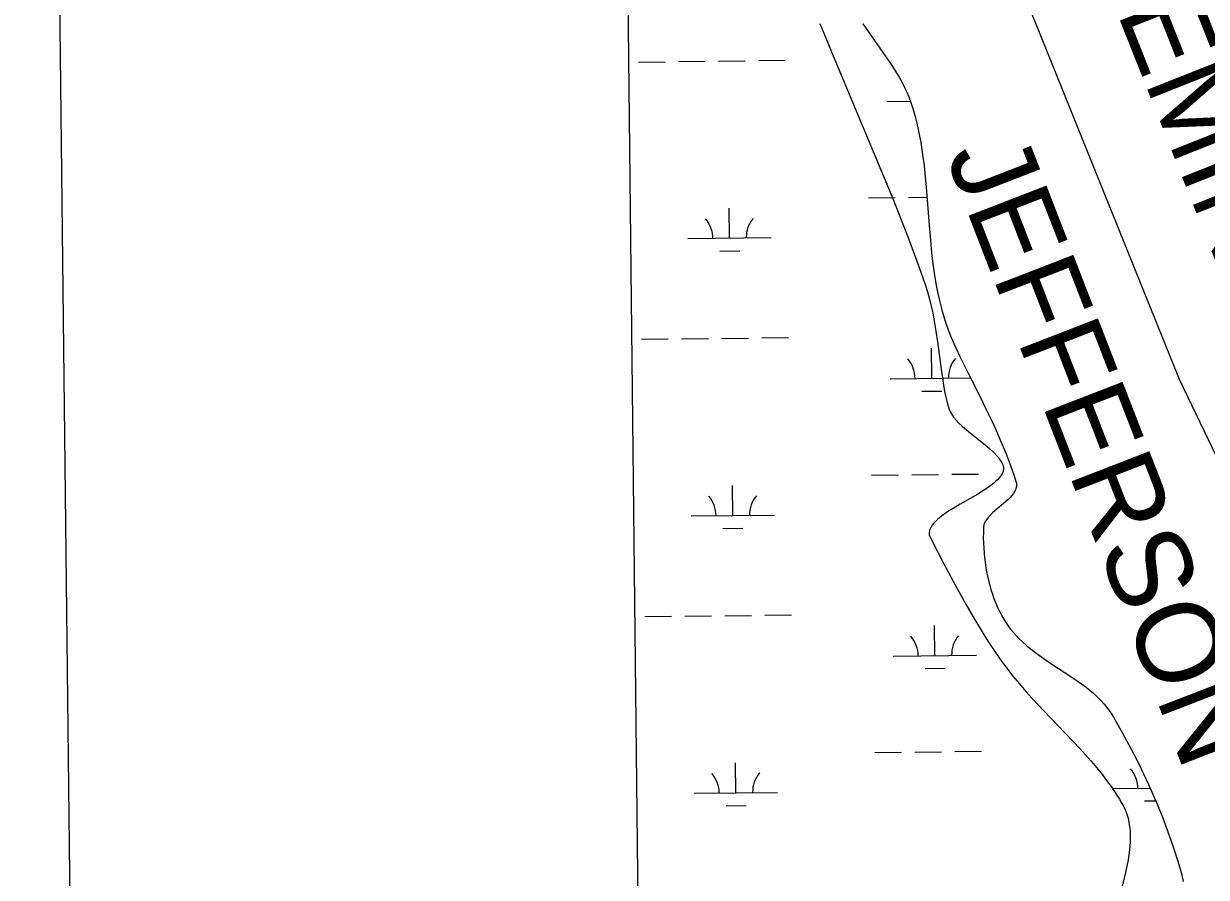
# Model space of a CAD drawing. Extents: x 3678539 to 3716648, y 451386 to 477139.
# Drawn here: x 3681880 to 3683298, y 470744 to 471768 of the extents above; entities that cross this region are included whole.
import ezdxf

# ---------------------------------------------------------------- set-up
doc = ezdxf.new("R2010")
doc.units = 0
for name, color, linetype in [('V-ANNO-SYMB', 7, 'Continuous'), ('V-GRID-FRAM', 7, 'Continuous'), ('V-SITE-VEGE', 7, 'Continuous'), ('V-TOPO-BNDY', 7, 'Continuous'), ('V-TOPO-GNAM-IDEN', 7, 'Continuous'), ('V-TOPO-SHOR', 7, 'Continuous'), ('V-WETL-SWMP', 7, 'Continuous')]:
    doc.layers.add(name, color=color, linetype=linetype)

msp = doc.modelspace()

# ---------------------------------------------------------------- linework, layer by layer
at = {"layer": 'V-ANNO-SYMB'}
msp.add_lwpolyline([(3682143.1, 452625.9), (3715224.1, 453006), (3714960.8, 475921.1), (3681879.8, 475540.9), (3682143.1, 452625.9)], dxfattribs=at)
at = {"layer": 'V-GRID-FRAM'}
msp.add_lwpolyline([(3682569.5, 474981.5), (3714284.1, 475345.9), (3714501, 457164.6), (3682770.5, 456800), (3682569.5, 474981.5)], dxfattribs=at)
at = {"layer": 'V-SITE-VEGE'}
for p, q in [((3682646.4, 468024.3), (3682598.3, 472383.5)), ((3682834.3, 471768.7), (3682850.4, 471729.6)), ((3682850.4, 471729.6), (3682907.7, 471593)), ((3682907.7, 471593), (3682921.7, 471558.7)), ((3682921.7, 471558.7), (3682931.9, 471533)), ((3682931.9, 471533), (3682939.4, 471513.7)), ((3682939.4, 471513.7), (3682950.3, 471484.7)), ((3682950.3, 471484.7), (3682955.5, 471470.1)), ((3682955.5, 471470.1), (3682960.7, 471455.5)), ((3682960.7, 471455.5), (3682963.6, 471446.5)), ((3682963.6, 471446.5), (3682966, 471437.7)), ((3682966, 471437.7), (3682968, 471429.3)), ((3682968, 471429.3), (3682969.7, 471421.3)), ((3682969.7, 471421.3), (3682971.1, 471413.7)), ((3682971.1, 471413.7), (3682973.4, 471399.3)), ((3682973.4, 471399.3), (3682975.3, 471386.7)), ((3682975.3, 471386.7), (3682980.1, 471350.9)), ((3682980.1, 471350.9), (3682982.6, 471334.6)), ((3682982.6, 471334.6), (3682984, 471327.1)), ((3682984, 471327.1), (3682985.1, 471321.8)), ((3682985.1, 471321.8), (3682987, 471314)), ((3682987, 471314), (3682989.1, 471306.7)), ((3682989.1, 471306.7), (3682989.9, 471304.5)), ((3682989.9, 471304.5), (3682990.9, 471302.3)), ((3682990.9, 471302.3), (3682992.1, 471300.2)), ((3682992.1, 471300.2), (3682993.4, 471298.2)), ((3682993.4, 471298.2), (3682994.8, 471296.3)), ((3682994.8, 471296.3), (3682997.9, 471292.5)), ((3682997.9, 471292.5), (3683001.2, 471289.1)), ((3683001.2, 471289.1), (3683004.5, 471285.9)), ((3683004.5, 471285.9), (3683007.9, 471282.9)), ((3683007.9, 471282.9), (3683014.5, 471277.3)), ((3683014.5, 471277.3), (3683026.7, 471267.7)), ((3683026.7, 471267.7), (3683035, 471260.9)), ((3683035, 471260.9), (3683038.1, 471258.2)), ((3683038.1, 471258.2), (3683042.9, 471253.7)), ((3683042.9, 471253.7), (3683046.4, 471250)), ((3683046.4, 471250), (3683048.8, 471247.3)), ((3683048.8, 471247.3), (3683050.3, 471245.2)), ((3683050.3, 471245.2), (3683052.2, 471242.1)), ((3683052.2, 471242.1), (3683053.7, 471239)), ((3683054, 471231), (3683052.9, 471228.5)), ((3683053.7, 471239), (3683054.2, 471237.6)), ((3683054.3, 471232.3), (3683054, 471231)), ((3683054.2, 471237.6), (3683054.4, 471236.2)), ((3683054.5, 471233.6), (3683054.3, 471232.3)), ((3683054.4, 471236.2), (3683054.5, 471234.9)), ((3683054.5, 471234.9), (3683054.5, 471233.6)), ((3683043, 471217.3), (3683037.8, 471213.2)), ((3683045.4, 471219.4), (3683043, 471217.3)), ((3683047.7, 471221.6), (3683045.4, 471219.4)), ((3683049.7, 471223.8), (3683047.7, 471221.6)), ((3683051.5, 471226.1), (3683049.7, 471223.8)), ((3683052.9, 471228.5), (3683051.5, 471226.1)), ((3683023.7, 471204.1), (3683002.7, 471191.9)), ((3683029.4, 471207.6), (3683023.7, 471204.1)), ((3683035, 471211.3), (3683029.4, 471207.6)), ((3683037.8, 471213.2), (3683035, 471211.3)), ((3683002.7, 471191.9), (3682994.3, 471186.9)), ((3682976, 471174), (3682972.9, 471171.2)), ((3682979.9, 471177.2), (3682976, 471174)), ((3682984.8, 471180.7), (3682979.9, 471177.2)), ((3682987.6, 471182.6), (3682984.8, 471180.7)), ((3682994.3, 471186.9), (3682987.6, 471182.6)), ((3682965.9, 471160.3), (3682965.5, 471158.1)), ((3682966.3, 471161.6), (3682965.9, 471160.3)), ((3682966.9, 471163), (3682966.3, 471161.6)), ((3682967.7, 471164.7), (3682966.9, 471163)), ((3682969, 471166.6), (3682967.7, 471164.7)), ((3682970.7, 471168.7), (3682969, 471166.6)), ((3682972.9, 471171.2), (3682970.7, 471168.7)), ((3682965.5, 471158.1), (3682965.5, 471156.4)), ((3682965.5, 471156.4), (3682965.6, 471155.2)), ((3682965.6, 471155.2), (3682966.1, 471153.3)), ((3682966.1, 471153.3), (3682967, 471151.4)), ((3682967, 471151.4), (3682983.2, 471120.4)), ((3682983.2, 471120.4), (3682997.5, 471093.6)), ((3682997.5, 471093.6), (3683009.5, 471071.9)), ((3683009.5, 471071.9), (3683019.8, 471054)), ((3683019.8, 471054), (3683027.8, 471040.7)), ((3683027.8, 471040.7), (3683033.9, 471030.8)), ((3683033.9, 471030.8), (3683038.6, 471023.5)), ((3683038.6, 471023.5), (3683045.7, 471012.8)), ((3683045.7, 471012.8), (3683053, 471002.4)), ((3683053, 471002.4), (3683057.2, 470996.7)), ((3683057.2, 470996.7), (3683065.5, 470986)), ((3683065.5, 470986), (3683073.7, 470976.2)), ((3683073.7, 470976.2), (3683081.5, 470967.2)), ((3683081.5, 470967.2), (3683089, 470958.9)), ((3683089, 470958.9), (3683103.3, 470943.6)), ((3683103.3, 470943.6), (3683128.6, 470917.3)), ((3683128.6, 470917.3), (3683138.1, 470907.4)), ((3683138.1, 470907.4), (3683146.2, 470898.7)), ((3683146.2, 470898.7), (3683153.2, 470891)), ((3683153.2, 470891), (3683159.2, 470884.1)), ((3683159.2, 470884.1), (3683164.3, 470878.1)), ((3683164.3, 470878.1), (3683173.1, 470867.3)), ((3683173.1, 470867.3), (3683179.4, 470859)), ((3683179.4, 470859), (3683183.9, 470852.7)), ((3683183.9, 470852.7), (3683190.5, 470843)), ((3683190.5, 470843), (3683193.6, 470838)), ((3683193.6, 470838), (3683196.6, 470833)), ((3683196.6, 470833), (3683198, 470830.4)), ((3683198, 470830.4), (3683200.5, 470825.3)), ((3683200.5, 470825.3), (3683202.4, 470820.2)), ((3683202.4, 470820.2), (3683203.9, 470815.2)), ((3683203.9, 470815.2), (3683205, 470810.2)), ((3683205, 470810.2), (3683205.8, 470805.3)), ((3683205.8, 470805.3), (3683206.3, 470800.5)), ((3683206.3, 470800.5), (3683206.5, 470795.8)), ((3683206.5, 470791.2), (3683206.4, 470786.6)), ((3683206.5, 470795.8), (3683206.5, 470791.2)), ((3683206.1, 470782.2), (3683205.1, 470773.6)), ((3683206.4, 470786.6), (3683206.1, 470782.2)), ((3683203.9, 470765.3), (3683202.4, 470757.6)), ((3683205.1, 470773.6), (3683203.9, 470765.3)), ((3683200.8, 470750.2), (3683191.7, 470712.2)), ((3683202.4, 470757.6), (3683200.8, 470750.2))]:
    msp.add_line(p, q, dxfattribs=at)
at = {"layer": 'V-TOPO-BNDY'}
for p, q in [((3682915.2, 472209.5), (3683265.3, 471341.7)), ((3683265.3, 471341.7), (3683528.6, 470791))]:
    msp.add_line(p, q, dxfattribs=at)
at = {"layer": 'V-TOPO-SHOR'}
for p, q in [((3682886.1, 471768.3), (3682889.9, 471762.5)), ((3682889.9, 471762.5), (3682919.8, 471719.3)), ((3682919.8, 471719.3), (3682923.4, 471713.8)), ((3682923.4, 471713.8), (3682929.3, 471704.1)), ((3682929.3, 471704.1), (3682933.5, 471696.8)), ((3682933.5, 471696.8), (3682936.3, 471691.1)), ((3682936.3, 471691.1), (3682938.3, 471686.9)), ((3682938.3, 471686.9), (3682941.1, 471680.4)), ((3682941.1, 471680.4), (3682943.5, 471673.7)), ((3682943.5, 471673.7), (3682946.2, 471665.3)), ((3682946.2, 471665.3), (3682948.5, 471657.1)), ((3682948.5, 471657.1), (3682950.6, 471649)), ((3682950.6, 471649), (3682952.4, 471641.2)), ((3682952.4, 471641.2), (3682953.9, 471633.5)), ((3682953.9, 471633.5), (3682955.3, 471626)), ((3682955.3, 471626), (3682957.6, 471611.4)), ((3682957.6, 471611.4), (3682959.3, 471597.6)), ((3682959.3, 471597.6), (3682960.7, 471584.6)), ((3682960.7, 471584.6), (3682961.9, 471572.3)), ((3682961.9, 471572.3), (3682965.5, 471526)), ((3682965.5, 471526), (3682966.9, 471508.7)), ((3682966.9, 471508.7), (3682968.4, 471493.6)), ((3682968.4, 471493.6), (3682969.9, 471480.4)), ((3682969.9, 471480.4), (3682971.5, 471469)), ((3682971.5, 471469), (3682973.1, 471459)), ((3682973.1, 471459), (3682974.7, 471450.4)), ((3682974.7, 471450.4), (3682976.2, 471442.9)), ((3682976.2, 471442.9), (3682977.7, 471436.4)), ((3682977.7, 471436.4), (3682980.5, 471425)), ((3682980.5, 471425), (3682983, 471416.6)), ((3682983, 471416.6), (3682985, 471410.4)), ((3682985, 471410.4), (3682988.3, 471401.1)), ((3682988.3, 471401.1), (3682992, 471391.9)), ((3682992, 471391.9), (3682997.6, 471379.3)), ((3682997.6, 471379.3), (3683002.7, 471368.3)), ((3683002.7, 471368.3), (3683012.1, 471349.2)), ((3683012.1, 471349.2), (3683026.5, 471320.7)), ((3683026.5, 471320.7), (3683033.6, 471306.4)), ((3683033.6, 471306.4), (3683040.5, 471291.9)), ((3683040.5, 471291.9), (3683044.6, 471282.9)), ((3683044.6, 471282.9), (3683051.5, 471267)), ((3683051.5, 471267), (3683056.4, 471255)), ((3683056.4, 471255), (3683060, 471246)), ((3683060, 471246), (3683065, 471232.5)), ((3683065, 471232.5), (3683067.3, 471225.8)), ((3683067.3, 471225.8), (3683069.5, 471219.2)), ((3683069.5, 471219.2), (3683070, 471217.3)), ((3683070, 471217.3), (3683070.2, 471215.5)), ((3683070.2, 471215.5), (3683070.2, 471213.8)), ((3683064.5, 471202.3), (3683062.4, 471199.9)), ((3683066.5, 471204.8), (3683064.5, 471202.3)), ((3683068.2, 471207.6), (3683066.5, 471204.8)), ((3683068.9, 471209.1), (3683068.2, 471207.6)), ((3683069.5, 471210.6), (3683068.9, 471209.1)), ((3683069.9, 471212.1), (3683069.5, 471210.6)), ((3683070.2, 471213.8), (3683069.9, 471212.1)), ((3683060.2, 471197.7), (3683041.4, 471181.5)), ((3683062.4, 471199.9), (3683060.2, 471197.7)), ((3683034.1, 471173.3), (3683032.8, 471171.2)), ((3683036.2, 471176.1), (3683034.1, 471173.3)), ((3683037.6, 471177.7), (3683036.2, 471176.1)), ((3683041.4, 471181.5), (3683037.6, 471177.7)), ((3683030.8, 471164.7), (3683030.5, 471158)), ((3683031.2, 471167.1), (3683030.8, 471164.7)), ((3683032, 471169.6), (3683031.2, 471167.1)), ((3683032.8, 471171.2), (3683032, 471169.6)), ((3683030.5, 471158), (3683030.4, 471151.5)), ((3683030.4, 471151.5), (3683030.6, 471145.2)), ((3683030.6, 471145.2), (3683030.9, 471139.1)), ((3683030.9, 471139.1), (3683031.3, 471133.3)), ((3683031.3, 471133.3), (3683031.8, 471127.8)), ((3683031.8, 471127.8), (3683032.5, 471122.5)), ((3683032.5, 471122.5), (3683034, 471112.6)), ((3683034, 471112.6), (3683035.7, 471103.9)), ((3683035.7, 471103.9), (3683037.6, 471096.3)), ((3683037.6, 471096.3), (3683039.5, 471089.7)), ((3683039.5, 471089.7), (3683041.3, 471083.9)), ((3683041.3, 471083.9), (3683043.1, 471078.9)), ((3683043.1, 471078.9), (3683044.7, 471074.6)), ((3683044.7, 471074.6), (3683047.9, 471067.2)), ((3683047.9, 471067.2), (3683050.6, 471061.8)), ((3683050.6, 471061.8), (3683052.7, 471057.9)), ((3683052.7, 471057.9), (3683056.1, 471052.1)), ((3683056.1, 471052.1), (3683059.8, 471046.5)), ((3683059.8, 471046.5), (3683063.1, 471042.1)), ((3683063.1, 471042.1), (3683066.4, 471038.1)), ((3683066.4, 471038.1), (3683069.7, 471034.4)), ((3683069.7, 471034.4), (3683073, 471030.9)), ((3683073, 471030.9), (3683076.4, 471027.6)), ((3683076.4, 471027.6), (3683083.1, 471021.6)), ((3683083.1, 471021.6), (3683089.7, 471016.2)), ((3683089.7, 471016.2), (3683096, 471011.5)), ((3683096, 471011.5), (3683102.1, 471007.1)), ((3683102.1, 471007.1), (3683113.8, 470999.3)), ((3683113.8, 470999.3), (3683134.3, 470986)), ((3683134.3, 470986), (3683141.9, 470980.9)), ((3683141.9, 470980.9), (3683148.3, 470976.3)), ((3683148.3, 470976.3), (3683153.8, 470972.2)), ((3683153.8, 470972.2), (3683158.5, 470968.5)), ((3683158.5, 470968.5), (3683162.4, 470965.1)), ((3683162.4, 470965.1), (3683165.8, 470962)), ((3683165.8, 470962), (3683171.4, 470956.4)), ((3683171.4, 470956.4), (3683175.4, 470952)), ((3683175.4, 470952), (3683178.2, 470948.6)), ((3683178.2, 470948.6), (3683182.2, 470943.1)), ((3683182.2, 470943.1), (3683185.9, 470937.4)), ((3683185.9, 470937.4), (3683191.8, 470927.1)), ((3683191.8, 470927.1), (3683197.3, 470917.4)), ((3683197.3, 470917.4), (3683207.2, 470899)), ((3683207.2, 470899), (3683215.5, 470882.8)), ((3683215.5, 470882.8), (3683222.5, 470868.5)), ((3683222.5, 470868.5), (3683228.4, 470855.8)), ((3683228.4, 470855.8), (3683233.4, 470844.7)), ((3683233.4, 470844.7), (3683237.6, 470834.9)), ((3683237.6, 470834.9), (3683244.7, 470817.6)), ((3683244.7, 470817.6), (3683249.7, 470804.5)), ((3683249.7, 470804.5), (3683253.3, 470794.6)), ((3683253.3, 470794.6), (3683258.5, 470779.7)), ((3683258.5, 470779.7), (3683263.4, 470764.7)), ((3683263.4, 470764.7), (3683266, 470755.7)), ((3683266, 470755.7), (3683268.2, 470747.3)), ((3683268.2, 470747.3), (3683270.1, 470739.3))]:
    msp.add_line(p, q, dxfattribs=at)
at = {"layer": 'V-WETL-SWMP'}
for p, q in [((3682647.2, 467956.8), (3682597.5, 472449.7)), ((3682886.1, 471768.3), (3682889.9, 471762.5)), ((3682889.9, 471762.5), (3682919.8, 471719.3)), ((3682616.9, 471722.3), (3682648.9, 471722.7)), ((3682664.9, 471722.9), (3682696.9, 471723.3)), ((3682712.9, 471723.4), (3682744.9, 471723.8)), ((3682760.9, 471724), (3682792.9, 471724.4)), ((3682919.8, 471719.3), (3682923.4, 471713.8)), ((3682923.4, 471713.8), (3682929.3, 471704.1)), ((3682929.3, 471704.1), (3682933.5, 471696.8)), ((3682933.5, 471696.8), (3682936.3, 471691.1)), ((3682936.3, 471691.1), (3682938.3, 471686.9)), ((3682938.3, 471686.9), (3682941.1, 471680.4)), ((3682914.7, 471675), (3682942.9, 471675.3)), ((3682941.1, 471680.4), (3682943.5, 471673.7)), ((3682943.5, 471673.7), (3682946.2, 471665.3)), ((3682946.2, 471665.3), (3682948.5, 471657.1)), ((3682948.5, 471657.1), (3682950.6, 471649)), ((3682950.6, 471649), (3682952.4, 471641.2)), ((3682952.4, 471641.2), (3682953.9, 471633.5)), ((3682953.9, 471633.5), (3682955.3, 471626)), ((3682955.3, 471626), (3682957.6, 471611.4)), ((3682957.6, 471611.4), (3682959.3, 471597.6)), ((3682959.3, 471597.6), (3682960.7, 471584.6)), ((3682960.7, 471584.6), (3682961.9, 471572.3)), ((3682961.9, 471572.3), (3682965.5, 471526)), ((3682892.7, 471559.3), (3682924.7, 471559.7)), ((3682940.7, 471559.9), (3682962.8, 471560.1)), ((3682726.1, 471511), (3682725.7, 471547)), ((3682965.5, 471526), (3682966.9, 471508.7)), ((3682676.1, 471510.4), (3682776.1, 471511.6)), ((3682966.9, 471508.7), (3682968.4, 471493.6)), ((3682714.3, 471495.4), (3682738.3, 471495.7)), ((3682968.4, 471493.6), (3682969.9, 471480.4)), ((3682969.9, 471480.4), (3682971.5, 471469)), ((3682971.5, 471469), (3682973.1, 471459)), ((3682973.1, 471459), (3682974.7, 471450.4)), ((3682974.7, 471450.4), (3682976.2, 471442.9)), ((3682976.2, 471442.9), (3682977.7, 471436.4)), ((3682977.7, 471436.4), (3682980.5, 471425)), ((3682980.5, 471425), (3682983, 471416.6)), ((3682983, 471416.6), (3682985, 471410.4)), ((3682985, 471410.4), (3682988.3, 471401.1)), ((3682988.3, 471401.1), (3682992, 471391.9)), ((3682620.7, 471389.7), (3682652.7, 471390.1)), ((3682668.7, 471390.2), (3682700.7, 471390.6)), ((3682716.7, 471390.8), (3682748.7, 471391.2)), ((3682764.7, 471391.3), (3682796.7, 471391.7)), ((3682992, 471391.9), (3682997.6, 471379.3)), ((3682968.6, 471342.9), (3682968.1, 471378.9)), ((3682997.6, 471379.3), (3683002.7, 471368.3)), ((3683002.7, 471368.3), (3683012.1, 471349.2)), ((3682918.6, 471342.4), (3683015, 471343.5)), ((3683012.1, 471349.2), (3683026.5, 471320.7)), ((3682956.7, 471327.4), (3682980.7, 471327.6)), ((3683026.5, 471320.7), (3683033.6, 471306.4)), ((3683033.6, 471306.4), (3683040.5, 471291.9)), ((3683040.5, 471291.9), (3683044.6, 471282.9)), ((3683044.6, 471282.9), (3683051.5, 471267)), ((3683051.5, 471267), (3683056.4, 471255)), ((3683056.4, 471255), (3683060, 471246)), ((3683060, 471246), (3683065, 471232.5)), ((3683065, 471232.5), (3683067.3, 471225.8)), ((3682896.5, 471226.7), (3682928.5, 471227)), ((3682944.5, 471227.2), (3682976.5, 471227.6)), ((3682992.5, 471227.8), (3683024.5, 471228.1)), ((3683067.3, 471225.8), (3683069.5, 471219.2)), ((3683069.5, 471219.2), (3683070, 471217.3)), ((3683070, 471217.3), (3683070.2, 471215.5)), ((3683070.2, 471215.5), (3683070.2, 471213.8)), ((3682730, 471178.3), (3682729.6, 471214.3)), ((3683064.5, 471202.3), (3683062.4, 471199.9)), ((3683066.5, 471204.8), (3683064.5, 471202.3)), ((3683068.2, 471207.6), (3683066.5, 471204.8)), ((3683068.9, 471209.1), (3683068.2, 471207.6)), ((3683069.5, 471210.6), (3683068.9, 471209.1)), ((3683069.9, 471212.1), (3683069.5, 471210.6)), ((3683070.2, 471213.8), (3683069.9, 471212.1)), ((3683060.2, 471197.7), (3683041.4, 471181.5)), ((3683062.4, 471199.9), (3683060.2, 471197.7)), ((3682680, 471177.8), (3682780, 471178.9)), ((3683034.1, 471173.3), (3683032.8, 471171.2)), ((3683036.2, 471176.1), (3683034.1, 471173.3)), ((3683037.6, 471177.7), (3683036.2, 471176.1)), ((3683041.4, 471181.5), (3683037.6, 471177.7)), ((3682718.1, 471162.8), (3682742.1, 471163)), ((3683030.8, 471164.7), (3683030.5, 471158)), ((3683031.2, 471167.1), (3683030.8, 471164.7)), ((3683032, 471169.6), (3683031.2, 471167.1)), ((3683032.8, 471171.2), (3683032, 471169.6)), ((3683030.5, 471158), (3683030.4, 471151.5)), ((3683030.4, 471151.5), (3683030.6, 471145.2)), ((3683030.6, 471145.2), (3683030.9, 471139.1)), ((3683030.9, 471139.1), (3683031.3, 471133.3)), ((3683031.3, 471133.3), (3683031.8, 471127.8)), ((3683031.8, 471127.8), (3683032.5, 471122.5)), ((3683032.5, 471122.5), (3683034, 471112.6)), ((3683034, 471112.6), (3683035.7, 471103.9)), ((3683035.7, 471103.9), (3683037.6, 471096.3)), ((3683037.6, 471096.3), (3683039.5, 471089.7)), ((3683039.5, 471089.7), (3683041.3, 471083.9)), ((3683041.3, 471083.9), (3683043.1, 471078.9)), ((3683043.1, 471078.9), (3683044.7, 471074.6)), ((3683044.7, 471074.6), (3683047.9, 471067.2)), ((3683047.9, 471067.2), (3683050.6, 471061.8)), ((3683050.6, 471061.8), (3683052.7, 471057.9)), ((3682624.5, 471057), (3682656.5, 471057.4)), ((3682672.5, 471057.6), (3682704.5, 471058)), ((3682720.5, 471058.1), (3682752.5, 471058.5)), ((3682768.5, 471058.7), (3682800.5, 471059.1)), ((3682972.4, 471010.3), (3682972, 471046.3)), ((3683052.7, 471057.9), (3683056.1, 471052.1)), ((3683056.1, 471052.1), (3683059.8, 471046.5)), ((3683059.8, 471046.5), (3683063.1, 471042.1)), ((3683063.1, 471042.1), (3683066.4, 471038.1)), ((3683066.4, 471038.1), (3683069.7, 471034.4)), ((3683069.7, 471034.4), (3683073, 471030.9)), ((3683073, 471030.9), (3683076.4, 471027.6)), ((3683076.4, 471027.6), (3683083.1, 471021.6)), ((3683083.1, 471021.6), (3683089.7, 471016.2)), ((3682922.4, 471009.7), (3683022.4, 471010.9)), ((3683089.7, 471016.2), (3683096, 471011.5)), ((3683096, 471011.5), (3683102.1, 471007.1)), ((3683102.1, 471007.1), (3683113.8, 470999.3)), ((3682960.6, 470994.7), (3682984.6, 470995)), ((3683113.8, 470999.3), (3683134.3, 470986)), ((3683134.3, 470986), (3683141.9, 470980.9)), ((3683141.9, 470980.9), (3683148.3, 470976.3)), ((3683148.3, 470976.3), (3683153.8, 470972.2)), ((3683153.8, 470972.2), (3683158.5, 470968.5)), ((3683158.5, 470968.5), (3683162.4, 470965.1)), ((3683162.4, 470965.1), (3683165.8, 470962)), ((3683165.8, 470962), (3683171.4, 470956.4)), ((3683171.4, 470956.4), (3683175.4, 470952)), ((3683175.4, 470952), (3683178.2, 470948.6)), ((3683178.2, 470948.6), (3683182.2, 470943.1)), ((3683182.2, 470943.1), (3683185.9, 470937.4)), ((3683185.9, 470937.4), (3683191.8, 470927.1)), ((3683191.8, 470927.1), (3683197.3, 470917.4)), ((3683197.3, 470917.4), (3683207.2, 470899)), ((3682900.3, 470894), (3682932.3, 470894.4)), ((3682948.3, 470894.6), (3682980.3, 470894.9)), ((3682996.3, 470895.1), (3683028.3, 470895.5)), ((3683207.2, 470899), (3683215.5, 470882.8)), ((3682733.8, 470845.7), (3682733.4, 470881.7)), ((3683215.5, 470882.8), (3683222.5, 470868.5)), ((3683222.5, 470868.5), (3683228.4, 470855.8)), ((3683185.7, 470850.9), (3683230.4, 470851.4)), ((3683228.4, 470855.8), (3683233.4, 470844.7)), ((3682683.8, 470845.1), (3682783.8, 470846.2)), ((3683223.8, 470835.9), (3683237.1, 470836)), ((3683233.4, 470844.7), (3683237.6, 470834.9)), ((3683237.6, 470834.9), (3683244.7, 470817.6)), ((3682722, 470830.1), (3682746, 470830.4)), ((3683244.7, 470817.6), (3683249.7, 470804.5)), ((3683249.7, 470804.5), (3683253.3, 470794.6)), ((3683253.3, 470794.6), (3683258.5, 470779.7)), ((3683258.5, 470779.7), (3683263.4, 470764.7)), ((3683263.4, 470764.7), (3683266, 470755.7)), ((3683266, 470755.7), (3683268.2, 470747.3)), ((3683268.2, 470747.3), (3683270.1, 470739.3))]:
    msp.add_line(p, q, dxfattribs=at)
for centre, start, end in [((3682670.9, 471510.8), 359.8865, 41.4302), ((3682781.4, 471512.1), 139.8865, 181.4302), ((3682913.3, 471342.8), 359.8865, 41.4302), ((3683023.8, 471344), 139.8865, 181.4302), ((3682674.7, 471178.2), 359.8865, 41.4302), ((3682785.2, 471179.4), 139.8865, 181.4302), ((3682917.1, 471010.1), 359.8865, 41.4302), ((3683027.6, 471011.4), 139.8865, 181.4302), ((3682678.5, 470845.5), 359.8865, 41.4302), ((3682789, 470846.8), 139.8865, 181.4302), ((3683180.4, 470851.3), 359.8865, 41.4302)]:
    msp.add_arc(centre, 35.2, start, end, dxfattribs=at)

# ---------------------------------------------------------------- texts
at = {"layer": 'V-TOPO-GNAM-IDEN'}
for s, rotation, p in [('PLAQUEMINES', 291.6367, (3683023, 472203.6)), ('JEFFERSON', 291.1803, (3682984.7, 471610.6))]:
    msp.add_text(s, height=100, rotation=rotation, dxfattribs=at).set_placement(p)

doc.saveas('drawing.dxf')
